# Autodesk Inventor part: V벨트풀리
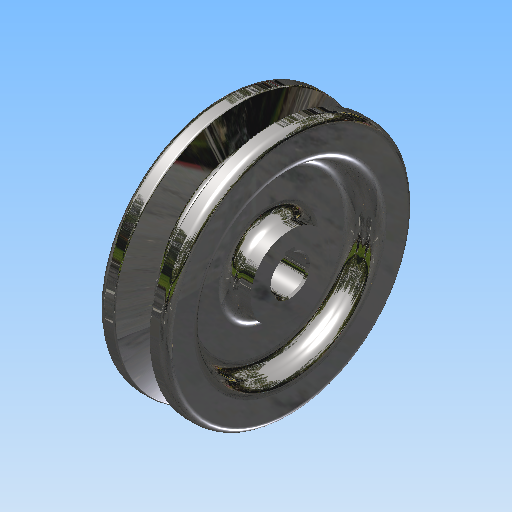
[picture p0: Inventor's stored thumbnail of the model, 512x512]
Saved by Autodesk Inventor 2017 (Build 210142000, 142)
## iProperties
Created: 2015-11
Part Number: V벨트풀리
Material: 강철, 탄소
Document SubType Name: Modeling
Designer: mduedu
Density: 1 g/cm^3
Appearance: 반광택
Author: mduedu
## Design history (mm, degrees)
sketch "스케치1"
  geometry: L1 (-9.5, 0)-(9.5, 0); L2 (0, 0)-(0, 34.7); L3 (-4.825, 34.7)-(-9.5, 34.7); L4 (-9.5, 34.7)-(-9.5, 0); L5 (0, 25.7)-(-2.074, 25.7); L6 (-2.074, 25.7)-(-4.825, 34.7); L7 (4.825, 34.7)-(9.5, 34.7); L8 (9.5, 34.7)-(9.5, 0); L9 (0, 25.7)-(2.074, 25.7); L10 (2.074, 25.7)-(4.825, 34.7); L11 (-9.5, 32)-(9.5, 32); 3 further points
  constraints: 22 end point, 7 point on line, 4 perpendicular, 3 symmetric about line, 1 coincident, 1 horizontal, 1 horizontal alignment, 1 midpoint, 1 vertical
  dimensions: "d0" = 19 distance of L1.start L1.end; "d2" = 69.4 diameter of L2.end L1 (derived); "d3" = 34 deg angle of L10 L6; "d4" = 6.3 distance between parallel lines of L11 L9; "d5" = 2.7 distance between parallel lines of L7 L11; "d6" = 8 distance of point (4, 32) point (-4, 32); "d7" = 64 diameter of L11 L1
revolve "회전1" sketch "스케치1" stored, may be unused: angle "d8" = 90 deg
sketch "스케치2"
  geometry: C1 r 24 at (0, 0); C2 r 11 at (0, 0); 1 further point
  constraints: 2 centre point, 2 coincident
  dimensions: "d9" = 48 diameter of C1; "d10" = 22 diameter of C2
extrude "돌출1" cut sketch "스케치2" distance "d11" = 6; taper "d12" = 0 deg
fillet "모깎기1" dims "d13" = 3
fillet "모깎기2" dims "d14" = 3
fillet "모깎기3" dims "d15" = 1, "d16" = 0.5, "d17" = 2
hole "구멍1" diameter "d20" = 10; stored, may be unused: countersink angle "d24" = 90 deg, drill point angle "d26" = 118 deg; dims "d18" = 10, "d19" = 10, "d21" = 6, "d22" = 4, "d23" = 2, "d25" = 8
sketch "스케치3"
  geometry: L1 (-1.5, 0)-(1.5, 0); L2 (1.5, 0)-(1.5, 6.4); L3 (1.5, 6.4)-(-1.5, 6.4); L4 (-1.5, 6.4)-(-1.5, 0); 2 further points
  constraints: 8 end point, 2 parallel, 1 coincident, 1 horizontal, 1 midpoint, 1 perpendicular
  dimensions: "d27" = 3 distance of L2.end L3.end; "d29" = 6.4 distance of L3.end L1.start
extrude "돌출2" cut sketch "스케치3" stored distance "d30" = 6; taper "d31" = 0 deg
chamfer "모따기1" distance "d32" = 0.5; stored, may be unused: second distance "d33" = 2, angle "d34" = 45 deg
node "솔리드1"
mirror "대칭1"
